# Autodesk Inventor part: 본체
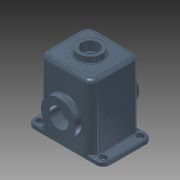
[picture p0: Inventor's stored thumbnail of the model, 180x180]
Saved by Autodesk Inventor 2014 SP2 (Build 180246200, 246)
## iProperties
Company: 한국ATC센터
Created: 2014-10
Part Number: 본체
Document SubType Name: Modeling
Designer: 한국ATC센터
Density: 2.71 g/cm^3
Material: 알루미늄 6061
Mass: 3285.44 g
Surface Area: 2358.48 cm^2
Volume: 1212.34 cm^3
Appearance: 청회색(진함/광택)
Author: KYOUNG IL JANG
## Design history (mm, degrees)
sketch "스케치1"
  geometry: L1 (-70, 65)-(70, 65); L2 (70, 65)-(70, -65); L3 (70, -65)-(-70, -65); L4 (-70, -65)-(-70, 65); 3 further points
  constraints: 8 end point, 2 midpoint, 2 parallel, 1 horizontal, 1 horizontal alignment, 1 perpendicular, 1 vertical alignment
  dimensions: "d0" = 140 distance of L2.end L3.end; "d68" = 130 distance of L3.end L1.start
extrude "돌출1" new body sketch "스케치1" distance "d1" = 180; taper "d2" = 0 deg
fillet "모깎기1" dims "d3" = 20
feature "쉘1" dims "d4" = 10
sketch "스케치2"
  geometry: L1 (-70, 45)-(-70, -45) reference; L2 (-50, -65)-(-82, -65); L3 (-82, 65)-(-50, 65); L4 (-85, 57)-(-82, 57); L5 (-82, 41)-(-85, 41); L6 (-100, 47)-(-100, -47); A1 r 20 centre (-50, 45) between (-50, 65) and (-70, 45) reference; A2 r 20 centre (-50, -45) between (-70, -45) and (-50, -65) reference; A3 r 8 centre (-82, 49) between (-82, 41) and (-82, 57); A4 r 8 centre (-85, 49) between (-85, 57) and (-85, 41); A5 r 18 centre (-82, 47) between (-82, 65) and (-100, 47); A6 r 18 centre (-82, -47) between (-100, -47) and (-82, -65); 1 further point
  constraints: 10 end point, 9 tangent, 8 point on circle, 4 centre point, 2 parallel, 2 perpendicular, 1 equal radius
  dimensions: "d6" = 49 vertical distance of point (0, 0) A3.centre; "d8" = 16 distance between parallel lines of L4 L5; "d64" = 18 radius of A5; "d65" = 12 distance from line of A3.centre L1; "d66" = 30 distance between parallel lines of L6 L1; "d67" = 3 distance of A4.centre A3.centre
extrude "돌출2" join sketch "스케치2" distance "d9" = 10; taper "d10" = 0 deg
extrude "돌출3" cut sketch "스케치2" stored distance "d11" = 10; taper "d12" = 0 deg
sketch "스케치3"
  geometry: L1 (-65, 0)-(-65, 180) reference; L2 (-55, 0)-(-55, 170) reference; L3 (-83, 75)-(-51, 75); L4 (45, 0)-(-45, 0) reference; L5 (-83, 75)-(-83, 120.5); L6 (-83, 120.5)-(-55, 120.5); L7 (-55, 120.5)-(-51, 116.5); L8 (-51, 116.5)-(-51, 75); 2 further points
  constraints: 10 end point, 4 perpendicular, 1 point on line
  dimensions: "d13" = 75 distance between parallel lines of L3 L4; "d14" = 18 distance from line of L1 L3.start; "d15" = 4 distance from line of L3.end L2; "d16" = 91 diameter of L6 L3; "d17" = 135 deg angle of L7 L2
revolve "회전1" sketch "스케치3" stored, may be unused: angle "d18" = 90 deg
sketch "스케치4"
  geometry: C1 r 45.5 at (0, 0) reference; 2 further points
  constraints: 1 vertical alignment
  dimensions: "d19" = 35 distance of C1.centre point (0, 35)
hole "구멍1" sketch "스케치4" at (0, 35) diameter "d20" = 3.459; stored, may be unused: countersink angle "d24" = 90 deg, drill point angle "d26" = 118 deg; dims "d21" = 13, "d22" = 4, "d23" = 2, "d25" = 16
fillet "모깎기2" dims "d30" = 3
hole "구멍2" diameter "d33" = 52; stored, may be unused: countersink angle "d37" = 90 deg, drill point angle "d39" = 118 deg; dims "d31" = 10, "d32" = 10, "d34" = 13, "d35" = 4, "d36" = 2, "d38" = 16
sketch "스케치5"
  geometry: C1 r 31 at (0, 0); 1 further point
  constraints: 1 centre point, 1 coincident
  dimensions: "d40" = 62 diameter of C1
extrude "돌출4" join sketch "스케치5" distance "d41" = 15; taper "d42" = 0 deg
hole "구멍3" diameter "d45" = 43; stored, may be unused: countersink angle "d49" = 90 deg, drill point angle "d51" = 118 deg; dims "d43" = 10, "d44" = 10, "d46" = 13, "d47" = 4, "d48" = 2, "d50" = 16
fillet "모깎기3" dims "d52" = 3
fillet "모깎기4" dims "d53" = 3
chamfer "모따기1" distance "d55" = 1; stored, may be unused: second distance "d56" = 2, angle "d57" = 45 deg
sketch "스케치6"
  geometry: 2 further points
  constraints: 1 vertical alignment, 1 other
  dimensions: "d71" = 90 distance of point (0, 0) point (0, 90)
feature "엠보싱2" sketch "스케치6" dims "d0" = 140, "d68" = 130, "d72" = 1, "d73" = 0
fillet "모깎기6" dims "d74" = 10
sketch "스케치7"
  geometry: C1 r 15 at (0, 0); C2 r 21.5 at (0, 0) reference; C3 r 25 at (0, 0); 1 further point
  constraints: 2 centre point, 2 coincident
  dimensions: "d61" = 30 diameter of C1; "d75" = 50 diameter of C3
extrude "돌출5" join sketch "스케치7" distance "d62" = 10; taper "d63" = 0 deg
feature "면 이동1" dims "d76" = 1
fillet "모깎기7" dims "d77" = 3
node "솔리드1"
mirror "대칭1"
mirror "대칭2"
pattern_circular "원형 패턴1" dims angle "d28" = 360 deg
mirror "대칭3"
